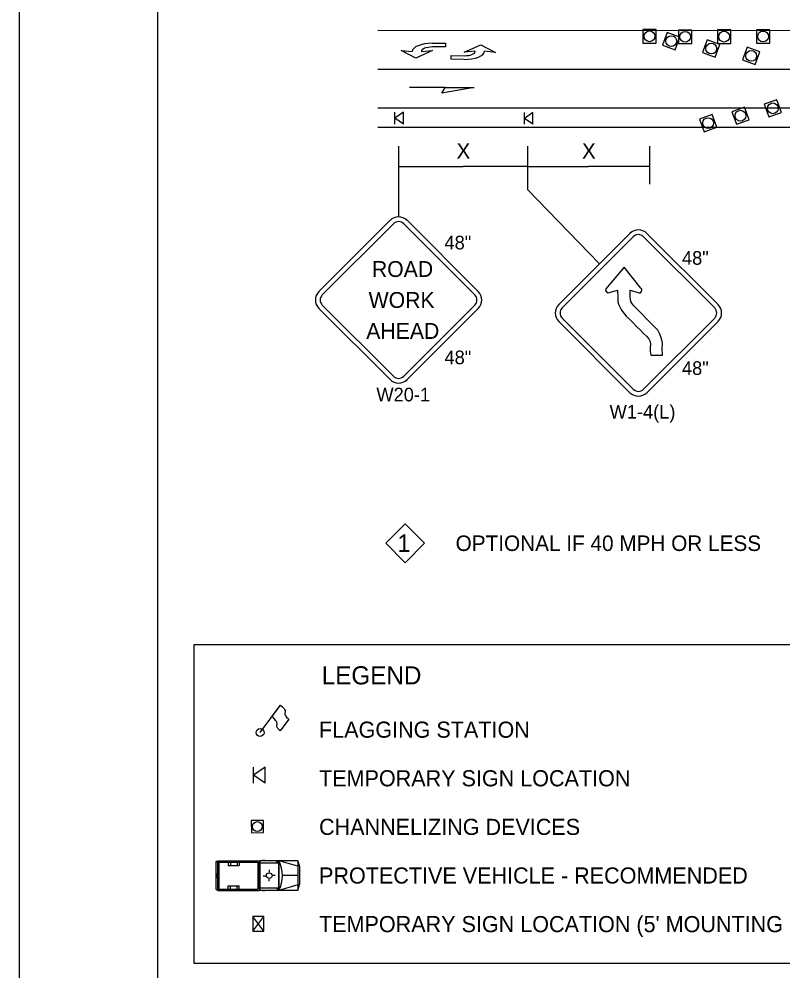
# Model space of a CAD drawing. Extents: x 99988 to 100172, y 99995 to 100047.
# Drawn here: x 99999.312 to 100003.104, y 100001.162 to 100005.887 of the extents above; entities that cross this region are included whole.
import ezdxf

# ---------------------------------------------------------------- set-up
doc = ezdxf.new("R2010")
doc.units = 0
for name, color, linetype in [('Default', 7, 'Continuous'), ('Level 15', 7, 'Continuous'), ('Level 20', 7, 'Continuous'), ('RD_MK_TrafficArrowType2LNew', 7, 'Continuous'), ('SH_DE_DetailBody1Text', 7, 'Continuous'), ('SH_DE_DetailHeading2Text', 7, 'Continuous'), ('SH_GI_PlotLimits', 7, 'Continuous'), ('SH_GI_SheetBorder', 7, 'Continuous'), ('SH_GI_TrafficMvmntArrowRt1Lane', 7, 'Continuous'), ('SH_TI_SignSpacing35to70Note', 7, 'Continuous'), ('TR_SN_WarningSigns', 7, 'Continuous'), ('TR_WZ_FlaggingStation', 7, 'Continuous'), ('TR_WZ_TrafficSafetyCone', 7, 'Continuous'), ('TR_WZ_TruckBuffer', 7, 'Continuous'), ('TR_WZ_WorkZoneDetails', 7, 'Continuous')]:
    doc.layers.add(name, color=color, linetype=linetype)

msp = doc.modelspace()

# ---------------------------------------------------------------- linework, layer by layer
at = {"layer": 'Default'}
for p, q in [((100005.7349, 100005.8272), (100001.0926, 100005.8307)), ((100001.2201, 100005.4254), (100001.1778, 100005.3958)), ((100001.1778, 100005.3664), (100001.1778, 100005.4254)), ((100001.2201, 100005.3664), (100001.2201, 100005.4254)), ((100001.8633, 100005.4238), (100001.821, 100005.3942)), ((100001.821, 100005.3648), (100001.821, 100005.4238)), ((100001.8633, 100005.3648), (100001.8633, 100005.4238)), ((100001.2201, 100005.3664), (100001.1778, 100005.3958)), ((100001.8633, 100005.3648), (100001.821, 100005.3942)), ((100000.5341, 100002.1741), (100000.4763, 100002.1338)), ((100000.4763, 100002.0937), (100000.4763, 100002.1741)), ((100000.5341, 100002.0937), (100000.5341, 100002.1741)), ((100000.5341, 100002.0937), (100000.4763, 100002.1338)), ((100000.4731, 100001.3598), (100000.5274, 100001.4323)), ((100000.5274, 100001.3598), (100000.4731, 100001.4323)), ((100000.5002, 100001.396), (100000.5002, 100001.396)), ((100000.5002, 100001.3959), (100000.5002, 100001.3959))]:
    msp.add_line(p, q, dxfattribs=at)
msp.add_lwpolyline([(100000.4731, 100001.3598), (100000.5274, 100001.3598), (100000.5274, 100001.4323), (100000.4731, 100001.4323)], close=True, dxfattribs=at)
at = {"layer": 'Level 15'}
for p, q in [((100001.1964, 100005.1555), (100001.5164, 100005.1555)), ((100001.8363, 100005.1555), (100001.5164, 100005.1555)), ((100001.8363, 100005.1555), (100002.1391, 100005.1555)), ((100002.4418, 100005.1555), (100002.1391, 100005.1555))]:
    msp.add_line(p, q, dxfattribs=at)
at = {"layer": 'RD_MK_TrafficArrowType2LNew'}
for p, q in [((100001.3643, 100005.7671), (100001.3643, 100005.7671)), ((100001.3643, 100005.7671), (100001.3643, 100005.7671)), ((100001.3643, 100005.7488), (100001.3643, 100005.7488)), ((100001.2635, 100005.7259), (100001.2635, 100005.7259)), ((100001.3093, 100005.7259), (100001.3093, 100005.7259)), ((100001.5216, 100005.7054), (100001.5216, 100005.7054)), ((100001.5768, 100005.7277), (100001.5768, 100005.7277)), ((100001.6227, 100005.7272), (100001.6227, 100005.7272)), ((100001.5214, 100005.687), (100001.5214, 100005.687)), ((100001.5214, 100005.687), (100001.5214, 100005.687))]:
    msp.add_line(p, q, dxfattribs=at)
for points in [[(100001.3643, 100005.7671), (100001.4285, 100005.7671), (100001.4285, 100005.7488), (100001.3643, 100005.7488)], [(100001.5768, 100005.7277), (100001.5218, 100005.7237), (100001.6047, 100005.7595), (100001.6776, 100005.7221), (100001.6227, 100005.7272)], [(100001.3093, 100005.7259), (100001.3643, 100005.7305), (100001.2818, 100005.6938), (100001.2085, 100005.7305), (100001.2635, 100005.7259)], [(100001.5214, 100005.687), (100001.4573, 100005.6877), (100001.4575, 100005.706), (100001.5216, 100005.7054)]]:
    msp.add_lwpolyline(points, dxfattribs=at)
for centre, major_axis, ratio, start_param in [((100001.3643, 100005.7259), (-0.1008, 0), 0.40879, 4.712524), ((100001.3643, 100005.7259), (-0.055, 0), 0.41611, 4.712518), ((100001.5218, 100005.7282), (0.1008, -0.001), 0.40879, 4.712524), ((100001.5218, 100005.7282), (0.055, -0.0006), 0.41611, 4.712518)]:
    msp.add_ellipse(centre, major_axis=major_axis, ratio=ratio, start_param=start_param, end_param=6.283185, dxfattribs=at)
at = {"layer": 'SH_DE_DetailBody1Text'}
msp.add_lwpolyline([(100001.2289, 100003.3821), (100001.3255, 100003.2855), (100001.2289, 100003.189), (100001.1324, 100003.2855)], close=True, dxfattribs=at)
at = {"layer": 'SH_GI_PlotLimits'}
msp.add_lwpolyline([(99999.3125, 99999.9375), (100015.8125, 99999.9375), (100015.8125, 100010.4375), (99999.3125, 100010.4375)], close=True, dxfattribs=at)
at = {"layer": 'SH_GI_SheetBorder'}
msp.add_line((100000, 100010.375), (100000, 100000), dxfattribs=at)
at = {"layer": 'SH_GI_TrafficMvmntArrowRt1Lane'}
msp.add_line((100001.4274, 100005.5469), (100001.2505, 100005.5469), dxfattribs=at)
msp.add_lwpolyline([(100001.5715, 100005.5469), (100001.411, 100005.5187), (100001.4274, 100005.5469)], close=True, dxfattribs=at)
at = {"layer": 'SH_TI_SignSpacing35to70Note'}
msp.add_lwpolyline([(100000.1818, 100002.782), (100003.8506, 100002.782), (100003.8506, 100001.1987), (100000.1818, 100001.1987)], close=True, dxfattribs=at)
at = {"layer": 'TR_SN_WarningSigns'}
for p, q in [((100000.8009, 100004.5349), (100001.1543, 100004.8883)), ((100001.2385, 100004.8883), (100001.5918, 100004.5349)), ((100000.8178, 100004.5181), (100001.1711, 100004.8715)), ((100001.2216, 100004.8715), (100001.575, 100004.5181)), ((100002.3446, 100004.8237), (100001.9912, 100004.4703)), ((100002.3614, 100004.8068), (100002.008, 100004.4534)), ((100002.7653, 100004.4534), (100002.4119, 100004.8068)), ((100002.7821, 100004.4703), (100002.4287, 100004.8237)), ((100001.1711, 100004.1142), (100000.8178, 100004.4676)), ((100001.575, 100004.4676), (100001.2216, 100004.1142)), ((100001.1543, 100004.0974), (100000.8009, 100004.4508)), ((100001.5918, 100004.4507), (100001.2384, 100004.0974)), ((100001.9912, 100004.3861), (100002.3446, 100004.0328)), ((100002.008, 100004.403), (100002.3614, 100004.0496)), ((100002.4119, 100004.0496), (100002.7653, 100004.403)), ((100002.4287, 100004.0328), (100002.7821, 100004.3861))]:
    msp.add_line(p, q, dxfattribs=at)
msp.add_lwpolyline([(100002.3166, 100004.6566), (100002.2252, 100004.5483), (100002.2237, 100004.5419), (100002.2277, 100004.5337), (100002.2362, 100004.5277), (100002.2439, 100004.5295), (100002.2835, 100004.541), (100002.2838, 100004.5017), (100002.2851, 100004.4839), (100002.2879, 100004.4724), (100002.2925, 100004.4614), (100002.3031, 100004.4427), (100002.3136, 100004.4281), (100002.3264, 100004.4129), (100002.342, 100004.3985), (100002.3592, 100004.3814), (100002.378, 100004.3617), (100002.3964, 100004.3439), (100002.4127, 100004.3266), (100002.4269, 100004.3138), (100002.4382, 100004.3004), (100002.4438, 100004.2896), (100002.4463, 100004.275), (100002.4444, 100004.2534), (100002.4457, 100004.2395), (100002.4476, 100004.2197), (100002.5069, 100004.2198), (100002.5051, 100004.2528), (100002.507, 100004.2745), (100002.5045, 100004.289), (100002.4997, 100004.305), (100002.4932, 100004.3237), (100002.4824, 100004.3433), (100002.4626, 100004.3628), (100002.3645, 100004.4645), (100002.3546, 100004.4763), (100002.3494, 100004.4851), (100002.3476, 100004.4968), (100002.3458, 100004.5045), (100002.3466, 100004.5418), (100002.391, 100004.5277), (100002.3965, 100004.5288), (100002.4006, 100004.5328), (100002.4045, 100004.5418), (100002.4033, 100004.5466), (100002.3981, 100004.5514)], close=True, dxfattribs=at)
for centre, radius, start, end in [((100001.1964, 100004.8462), 0.0595, 44.9963, 134.9997), ((100001.1964, 100004.8462), 0.0357, 44.9963, 134.9997), ((100002.3867, 100004.7816), 0.0595, 44.9963, 134.9997), ((100002.3867, 100004.7816), 0.0357, 44.9963, 134.9997), ((100000.843, 100004.4928), 0.0595, 134.9966, 224.9936), ((100000.843, 100004.4928), 0.0357, 134.9966, 224.9936), ((100001.5498, 100004.4928), 0.0357, 314.9994, 44.9948), ((100001.5498, 100004.4928), 0.0595, 314.9994, 44.9948), ((100002.0333, 100004.4282), 0.0595, 134.9966, 224.9936), ((100002.74, 100004.4282), 0.0595, 314.9994, 44.9948), ((100002.0333, 100004.4282), 0.0357, 134.9966, 224.9936), ((100002.7401, 100004.4282), 0.0357, 314.9994, 44.9948), ((100001.1964, 100004.1395), 0.0595, 225, 314.9996), ((100001.1964, 100004.1395), 0.0357, 225, 314.9996), ((100002.3867, 100004.0748), 0.0357, 225, 314.9996), ((100002.3867, 100004.0748), 0.0595, 225, 314.9996)]:
    msp.add_arc(centre, radius, start, end, dxfattribs=at)
at = {"layer": 'TR_WZ_FlaggingStation'}
for p, q in [((100000.509, 100002.3458), (100000.6099, 100002.4821)), ((100000.569, 100002.4268), (100000.6101, 100002.4823)), ((100000.569, 100002.4268), (100000.569, 100002.4268)), ((100000.651, 100002.4117), (100000.6089, 100002.3548))]:
    msp.add_line(p, q, dxfattribs=at)
for points in [[(100000.6101, 100002.4823), (100000.6127, 100002.4799), (100000.6209, 100002.4728), (100000.6268, 100002.4665), (100000.63, 100002.4604), (100000.633, 100002.4554), (100000.6339, 100002.4501), (100000.6338, 100002.4448), (100000.6322, 100002.4414), (100000.6322, 100002.435), (100000.6356, 100002.4279), (100000.6405, 100002.4215), (100000.651, 100002.4117)], [(100000.6089, 100002.3548), (100000.6051, 100002.3579), (100000.5973, 100002.3657), (100000.5923, 100002.3758), (100000.5921, 100002.3833), (100000.5932, 100002.3898), (100000.5917, 100002.3982), (100000.5879, 100002.4047), (100000.581, 100002.4136), (100000.569, 100002.4268)]]:
    msp.add_lwpolyline(points, dxfattribs=at)
msp.add_circle((100000.509, 100002.3458), 0.0195, dxfattribs=at)
at = {"layer": 'TR_WZ_TrafficSafetyCone'}
for points in [[(100002.4084, 100005.7685), (100002.4752, 100005.7685), (100002.4752, 100005.8353), (100002.4084, 100005.8353)], [(100002.5854, 100005.7659), (100002.6522, 100005.7659), (100002.6522, 100005.8327), (100002.5854, 100005.8327)], [(100002.7788, 100005.7667), (100002.8456, 100005.7667), (100002.8456, 100005.8335), (100002.7788, 100005.8335)], [(100002.9722, 100005.7675), (100003.039, 100005.7675), (100003.039, 100005.8343), (100002.9722, 100005.8343)], [(100002.5071, 100005.7579), (100002.5699, 100005.7351), (100002.5928, 100005.7979), (100002.53, 100005.8207)], [(100002.7055, 100005.7212), (100002.7683, 100005.6983), (100002.7912, 100005.7611), (100002.7284, 100005.784)], [(100002.9039, 100005.6844), (100002.9667, 100005.6616), (100002.9896, 100005.7243), (100002.9268, 100005.7472)], [(100003.0339, 100005.4014), (100003.0967, 100005.4242), (100003.0739, 100005.487), (100003.0111, 100005.4641)], [(100002.7127, 100005.3282), (100002.7755, 100005.351), (100002.7527, 100005.4138), (100002.6899, 100005.391)], [(100002.8733, 100005.3648), (100002.9361, 100005.3876), (100002.9133, 100005.4504), (100002.8505, 100005.4276)], [(100000.5253, 100001.91), (100000.4646, 100001.9089), (100000.4656, 100001.8482), (100000.5263, 100001.8492)]]:
    msp.add_lwpolyline(points, close=True, dxfattribs=at)
for centre, radius in [((100002.4418, 100005.8019), 0.0268), ((100002.55, 100005.7779), 0.0268), ((100002.6188, 100005.7993), 0.0268), ((100002.8122, 100005.8001), 0.0268), ((100003.0056, 100005.8009), 0.0268), ((100002.7484, 100005.7411), 0.0268), ((100002.9467, 100005.7044), 0.0268), ((100003.0539, 100005.4442), 0.0268), ((100002.8933, 100005.4076), 0.0268), ((100002.7327, 100005.371), 0.0268), ((100000.4955, 100001.8791), 0.0244)]:
    msp.add_circle(centre, radius, dxfattribs=at)
at = {"layer": 'TR_WZ_TruckBuffer'}
for p, q in [((100000.289, 100001.702), (100000.2889, 100001.5694)), ((100000.2935, 100001.7064), (100000.2979, 100001.7064)), ((100000.2979, 100001.7064), (100000.2979, 100001.5649)), ((100000.2986, 100001.7088), (100000.2985, 100001.5625)), ((100000.2986, 100001.7088), (100000.5044, 100001.7087)), ((100000.3045, 100001.703), (100000.3044, 100001.5683)), ((100000.3045, 100001.703), (100000.4985, 100001.7029)), ((100000.3508, 100001.703), (100000.3508, 100001.6861)), ((100000.3508, 100001.6861), (100000.4058, 100001.6861)), ((100000.3618, 100001.7029), (100000.3618, 100001.6861)), ((100000.3958, 100001.7029), (100000.3958, 100001.6861)), ((100000.4058, 100001.7029), (100000.4058, 100001.6861)), ((100000.4985, 100001.7029), (100000.4984, 100001.5682)), ((100000.5044, 100001.7087), (100000.5043, 100001.5624)), ((100000.5071, 100001.7087), (100000.507, 100001.5624)), ((100000.696, 100001.7086), (100000.5071, 100001.7087)), ((100000.5998, 100001.6973), (100000.5071, 100001.6974)), ((100000.5329, 100001.7107), (100000.5215, 100001.7107)), ((100000.5998, 100001.7086), (100000.5878, 100001.6973)), ((100000.5998, 100001.7086), (100000.5998, 100001.5623)), ((100000.6016, 100001.7086), (100000.6015, 100001.5623)), ((100000.696, 100001.6818), (100000.6016, 100001.7086)), ((100000.696, 100001.7086), (100000.6959, 100001.5623)), ((100000.696, 100001.7086), (100000.7053, 100001.679)), ((100000.7053, 100001.679), (100000.7052, 100001.5918)), ((100000.289, 100001.646), (100000.2979, 100001.6432)), ((100000.289, 100001.6254), (100000.2979, 100001.6281)), ((100000.2914, 100001.6357), (100000.2955, 100001.6357)), ((100000.2934, 100001.6377), (100000.2934, 100001.6336)), ((100000.5236, 100001.635), (100000.5385, 100001.6352)), ((100000.5404, 100001.6353), (100000.5404, 100001.6353)), ((100000.5545, 100001.6645), (100000.5545, 100001.6527)), ((100000.5846, 100001.6356), (100000.572, 100001.6356)), ((100000.696, 100001.6354), (100000.6201, 100001.6355)), ((100000.3508, 100001.5683), (100000.3508, 100001.5851)), ((100000.3508, 100001.5851), (100000.4057, 100001.5851)), ((100000.3617, 100001.5683), (100000.3618, 100001.5851)), ((100000.3957, 100001.5683), (100000.3958, 100001.5851)), ((100000.4057, 100001.5683), (100000.4057, 100001.5851)), ((100000.5537, 100001.6074), (100000.554, 100001.6184)), ((100000.6959, 100001.5891), (100000.6015, 100001.5623)), ((100000.6959, 100001.5623), (100000.7052, 100001.5918)), ((100000.2934, 100001.5649), (100000.2979, 100001.5649)), ((100000.2985, 100001.5625), (100000.5043, 100001.5624)), ((100000.3044, 100001.5683), (100000.4984, 100001.5682)), ((100000.5998, 100001.5737), (100000.507, 100001.5737)), ((100000.6959, 100001.5623), (100000.507, 100001.5624)), ((100000.5328, 100001.5603), (100000.5214, 100001.5603)), ((100000.5898, 100001.5737), (100000.5998, 100001.5623))]:
    msp.add_line(p, q, dxfattribs=at)
for centre, radius in [((100000.2934, 100001.6357), 0.00206), ((100000.5545, 100001.6355), 0.0141)]:
    msp.add_circle(centre, radius, dxfattribs=at)
for centre, radius, start, end in [((100000.2935, 100001.702), 0.00446, 89.9656, 179.9656), ((100000.4665, 100001.6355), 0.1535, 331.5161, 28.4256), ((100000.2934, 100001.5694), 0.00446, 179.9656, 269.9656)]:
    msp.add_arc(centre, radius, start, end, dxfattribs=at)
at = {"layer": 'TR_WZ_WorkZoneDetails'}
for p, q in [((100001.0926, 100005.6386), (100006.4262, 100005.6386)), ((100001.0926, 100005.4465), (100002.7834, 100005.4465)), ((100002.281, 100005.4465), (100005.7015, 100005.4465)), ((100001.0926, 100005.3505), (100002.7834, 100005.3505)), ((100002.281, 100005.3505), (100006.1907, 100005.3505)), ((100001.1964, 100005.2564), (100001.1964, 100004.9057)), ((100001.8363, 100005.2564), (100001.8363, 100005.0417)), ((100002.4418, 100005.2564), (100002.4418, 100005.0675)), ((100001.8363, 100005.0417), (100002.194, 100004.6731))]:
    msp.add_line(p, q, dxfattribs=at)

# ---------------------------------------------------------------- texts
at = {"layer": 'Level 20'}
for p in [(100001.4837, 100005.194), (100002.1064, 100005.194)]:
    msp.add_text('X', height=0.077, rotation=360, dxfattribs=at).set_placement(p)
at = {"layer": 'SH_DE_DetailBody1Text'}
for s, height, p in [('1', 0.088, (100001.1904, 100003.2415)), ('OPTIONAL IF 40 MPH OR LESS', 0.077, (100001.4795, 100003.247)), ('FLAGGING STATION', 0.08, (100000.8016, 100002.3201)), ('TEMPORARY SIGN LOCATION', 0.08, (100000.8016, 100002.0788)), ('CHANNELIZING DEVICES', 0.08, (100000.8016, 100001.8375)), ('PROTECTIVE VEHICLE - RECOMMENDED', 0.08, (100000.8016, 100001.5962)), ("TEMPORARY SIGN LOCATION (5' MOUNTING HEIGHT)", 0.08, (100000.8016, 100001.3549))]:
    msp.add_text(s, height=height, dxfattribs=at).set_placement(p)
at = {"layer": 'SH_DE_DetailHeading2Text'}
msp.add_text('LEGEND', height=0.09, dxfattribs=at).set_placement((100000.8148, 100002.5848))
at = {"layer": 'TR_SN_WarningSigns'}
for s, height, p in [('48"', 0.06768, (100001.4242, 100004.744)), ('48"', 0.06768, (100002.6029, 100004.6678)), ('ROAD', 0.0787, (100001.0639, 100004.6072)), ('WORK', 0.0787, (100001.0477, 100004.4535)), ('AHEAD', 0.0787, (100001.0359, 100004.2998)), ('48"', 0.06768, (100001.4242, 100004.174)), ('48"', 0.06768, (100002.6029, 100004.1209)), ('W20-1', 0.06768, (100001.0862, 100003.9896)), ('W1-4(L)', 0.06768, (100002.2437, 100003.9041))]:
    msp.add_text(s, height=height, dxfattribs=at).set_placement(p)

doc.saveas('drawing.dxf')
